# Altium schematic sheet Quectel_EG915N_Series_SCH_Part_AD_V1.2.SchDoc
size A2; Organization: Altium Limited; Address1: L3, 12a Rodborough Rd; Address2: Frenchs Forest; Address3: NSW; Address4: Australia 2086
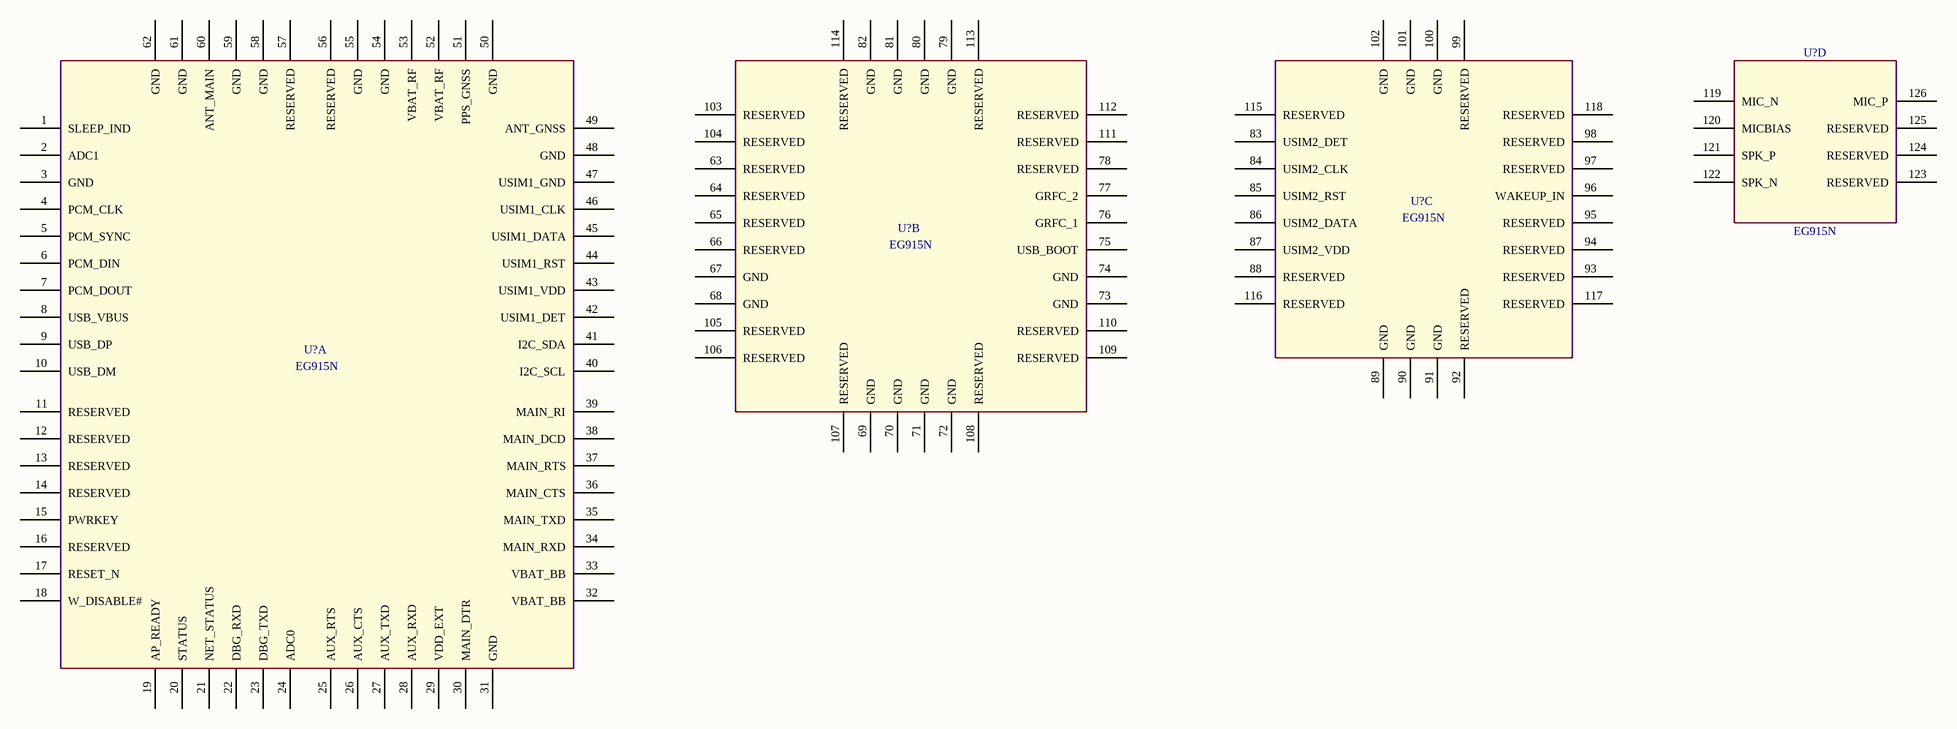
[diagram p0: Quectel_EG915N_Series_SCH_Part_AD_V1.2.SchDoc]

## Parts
(Parts that share a designator on the sheet are numbered #1, #2 ... from top to bottom, then left to right.)
U?#1  EG915N  [EG915N]  (part D of 4)
U?#2  EG915N  [EG915N]  (part C of 4)
U?#3  EG915N  [EG915N]  (part B of 4)
U?#4  EG915N  [EG915N]  (part A of 4)

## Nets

Not connected (* = marked no-connect by the designer): U?#1 119(MIC_N) 120(MICBIAS) 121(SPK_P) 122(SPK_N) 123(RESERVED) 124(RESERVED) 125(RESERVED) 126(MIC_P); U?#2 83(USIM2_DET) 84(USIM2_CLK) 85(USIM2_RST) 86(USIM2_DATA) 87(USIM2_VDD) 88(RESERVED) 89(GND) 90(GND) 91(GND) 92(RESERVED) 93(RESERVED) 94(RESERVED) 95(RESERVED) 96(WAKEUP_IN) 97(RESERVED) 98(RESERVED) 99(RESERVED) 100(GND) 101(GND) 102(GND) 115(RESERVED) 116(RESERVED) 117(RESERVED) 118(RESERVED); U?#3 63(RESERVED) 64(RESERVED) 65(RESERVED) 66(RESERVED) 67(GND) 68(GND) 69(GND) 70(GND) 71(GND) 72(GND) 73(GND) 74(GND) 75(USB_BOOT) 76(GRFC_1) 77(GRFC_2) 78(RESERVED) 79(GND) 80(GND) 81(GND) 82(GND) 103(RESERVED) 104(RESERVED) 105(RESERVED) 106(RESERVED) 107(RESERVED) 108(RESERVED) 109(RESERVED) 110(RESERVED) 111(RESERVED) 112(RESERVED) 113(RESERVED) 114(RESERVED); U?#4 1(SLEEP_IND) 2(ADC1) 3(GND) 4(PCM_CLK) 5(PCM_SYNC) 6(PCM_DIN) 7(PCM_DOUT) 8(USB_VBUS) 9(USB_DP) 10(USB_DM) 11(RESERVED) 12(RESERVED) 13(RESERVED) 14(RESERVED) 15(PWRKEY) 16(RESERVED) 17(RESET_N) 18(W_DISABLE#) 19(AP_READY) 20(STATUS) 21(NET_STATUS) 22(DBG_RXD) 23(DBG_TXD) 24(ADC0) 25(AUX_RTS) 26(AUX_CTS) 27(AUX_TXD) 28(AUX_RXD) 29(VDD_EXT) 30(MAIN_DTR) 31(GND) 32(VBAT_BB) 33(VBAT_BB) 34(MAIN_RXD) 35(MAIN_TXD) 36(MAIN_CTS) 37(MAIN_RTS) 38(MAIN_DCD) 39(MAIN_RI) 40(I2C_SCL) 41(I2C_SDA) 42(USIM1_DET) 43(USIM1_VDD) 44(USIM1_RST) 45(USIM1_DATA) 46(USIM1_CLK) 47(USIM1_GND) 48(GND) 49(ANT_GNSS) 50(GND) 51(PPS_GNSS) 52(VBAT_RF) 53(VBAT_RF) 54(GND) 55(GND) 56(RESERVED) 57(RESERVED) 58(GND) 59(GND) 60(ANT_MAIN) 61(GND) 62(GND)

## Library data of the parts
U?#1-U?#4 = EG915N: EG915N Module LGA126Pin 19.9x23.6mm H2.4mm RO; Manufacturer: Quectel; Geometry.Height: 2.4mm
